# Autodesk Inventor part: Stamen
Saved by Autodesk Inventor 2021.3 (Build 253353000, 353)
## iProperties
Created: 2022-07
Part Number: Stamen
Material: Generic
Document SubType Name: Modeling
Designer: Administrator
Density: 1 g/cm^3
Appearance: Default
Title: Stamen v3
Author: Administrator
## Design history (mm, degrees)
feature "Stamen_" [Body]
feature "Socket Body" [Body]
feature "Shade Ring" [Body]
feature "Shade Ring +Collar" [Body]
feature "Socket" [Body]
feature "Body1"
feature "Metal Strain Relief" [Body]
feature "Fabric Cord (1)" [Body]
feature "Stem (Threaded)" [Body]
feature "Cap (Threaded)" [Body]
feature "5M Set Screw" [Body]
feature "T8-Bulb" [Body]
body "Solid1"
body "Solid2"
body "Solid3"
body "Solid4"
body "Solid5"
body "Solid6"
body "Solid7"
body "Solid8"
body "Solid9"
body "Solid10"
body "Solid11"
body "Solid12"
